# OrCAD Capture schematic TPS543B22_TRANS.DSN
size D; title: TPS543B22 4V to 18V Input, 20A Synchronous Step-Down Converter; rev: 1.0; note: Datasheet: SLVSFW2A EVM: SLUUCH6B; note: with Internally Compensated Advanced CurrentMode Control
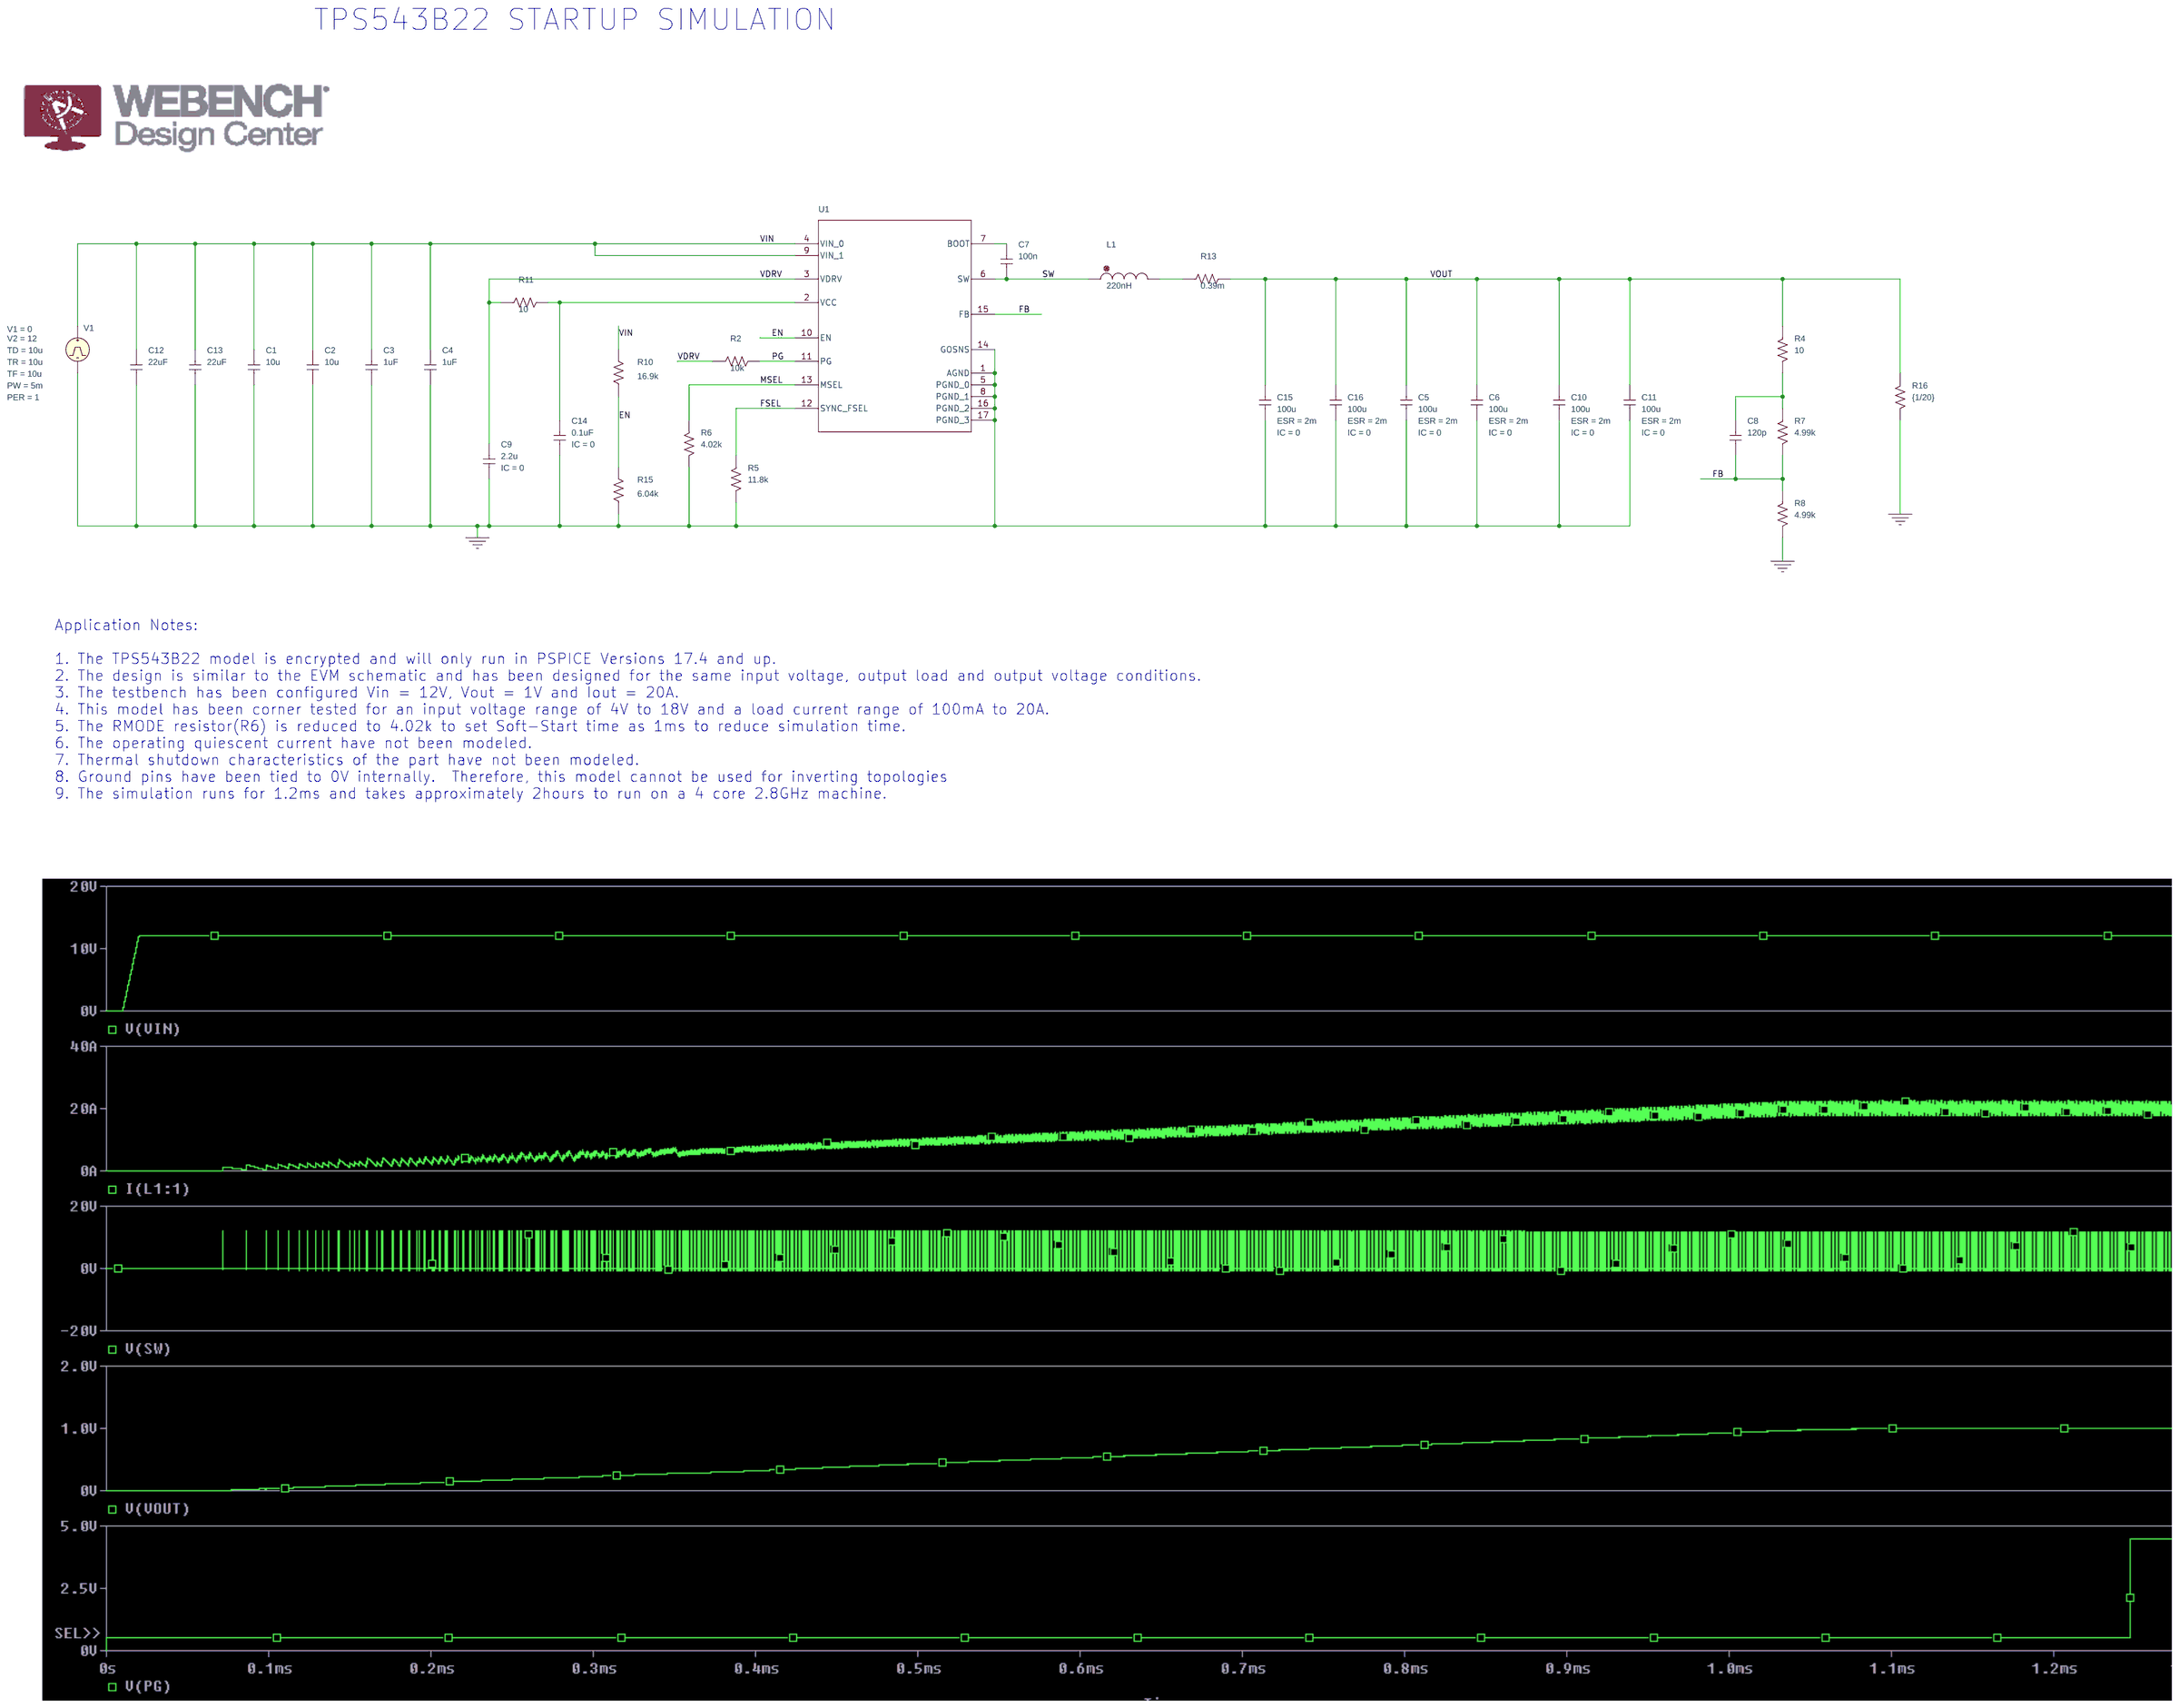
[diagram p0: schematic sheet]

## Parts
C1  10u  [cap196]
C2  10u  [cap196]
C3  1uF  [cap196]
C4  1uF  [cap196]
C5  100u  [RAD/CK05]
C6  100u  [RAD/CK05]
C7  100n  [cap196]
C8  120p  [cap196]
C9  2.2u  [cap196]
C10  100u  [RAD/CK05]
C11  100u  [RAD/CK05]
C12  22uF  [cap196]
C13  22uF  [cap196]
C14  0.1uF  [cap196]
C15  100u  [RAD/CK05]
C16  100u  [RAD/CK05]
L1  220nH  [DISC350x175LS200x100034]
R2  10k  [AXRC05]
R4  10  [AXRC05]
R5  11.8k  [AXRC05]
R6  4.02k  [AXRC05]
R7  4.99k  [AXRC05]
R8  4.99k  [AXRC05]
R10  16.9k  [AXRC05]
R11  10  [AXRC05]
R13  0.39m  [AXRC05]
R15  6.04k  [AXRC05]
R16  {1/20}  [AXRC05]
U1  Value  [RYS0017A-MFG]
V1  VPULSE

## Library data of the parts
C1-C4 C7 C8 C12 C13 = C
C5 C6 C10 C11 C15 C16 = C: AppProp: InductiveSlave:;SRF:;PrevCap:22u;PrevESL:; ESR: 2m; IC: 0
C9 C14 = C: IC: 0
L1 = L
R2 R4-R8 R10 R11 R13 R15 R16 = R
U1 = TPS543B22RYS_TRANS: PSpiceTemplate: X^@REFDES  %SYNC_FSEL %VCC %PGND_0 %FB %VIN_1 %EN %PG %MSEL %VDRV %SW %BOOT %GOSNS %AGND %PGND_1 %PGND_2 %PGND_3 %VIN_0 @MODEL
V1 = VPULSE: PER: 1; PW: 5m; TD: 10u; TF: 10u; TR: 10u; V1: 0; V2: 12

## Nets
VIN: C1.1 C2.1 C3.1 C4.1 C12.1 C13.1 R10.2 U1.4(VIN_0) U1.9(VIN_1) V1.1(+)
0: C1.2 C2.2 C3.2 C4.2 C5.2 C6.2 C9.2 C10.2 C11.2 C12.2 C13.2 C14.2 C15.2 C16.2 R5.2 R6.2 R8.2 R15.1 R16.2 U1.1(AGND) U1.5(PGND_0) U1.8(PGND_1) U1.14(GOSNS) U1.16(PGND_2) U1.17(PGND_3) V1.2(-)
EN: R10.1 R15.2 U1.10(EN)
FB: C8.2 R7.2 R8.1 U1.15(FB)
FSEL: R5.1 U1.12(SYNC_FSEL)
MSEL: R6.1 U1.13(MSEL)
PG: R2.2 U1.11(PG)
SW: C7.2 L1.1 U1.6(SW)
VDRV: C9.1 R2.1 R11.1 U1.3(VDRV)
VOUT: C5.1 C6.1 C10.1 C11.1 C15.1 C16.1 R4.1 R13.2 R16.1
N16770086: C14.1 R11.2 U1.2(VCC)
N16771999: C7.1 U1.7(BOOT)
N16772420: C8.1 R4.2 R7.1
N16836926: L1.2 R13.1

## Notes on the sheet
- TPS543B22 STARTUP SIMULATION
- Application Notes:
  1. The TPS543B22 model is encrypted and will only run in PSPICE Versions 17.4 and up.
  2. The design is similar to the EVM schematic and has been designed for the same input voltage, output load and output voltage conditions.
  3. The testbench has been configured Vin = 12V, Vout = 1V and Iout = 20A.
  4. This model has been corner tested for an input voltage range of 4V to 18V and a load current range of 100mA to 20A.
  5. The RMODE resistor(R6) is reduced to 4.02k to set Soft-Start time as 1ms to reduce simulation time.
  6. The operating quiescent current have not been modeled.
  7. Thermal shutdown characteristics of the part have not been modeled.
  8. Ground pins have been tied to 0V internally.  Therefore, this model cannot be used for inverting topologies
  9. The simulation runs for 1.2ms and takes approximately 2hours to run on a 4 core 2.8GHz machine.
